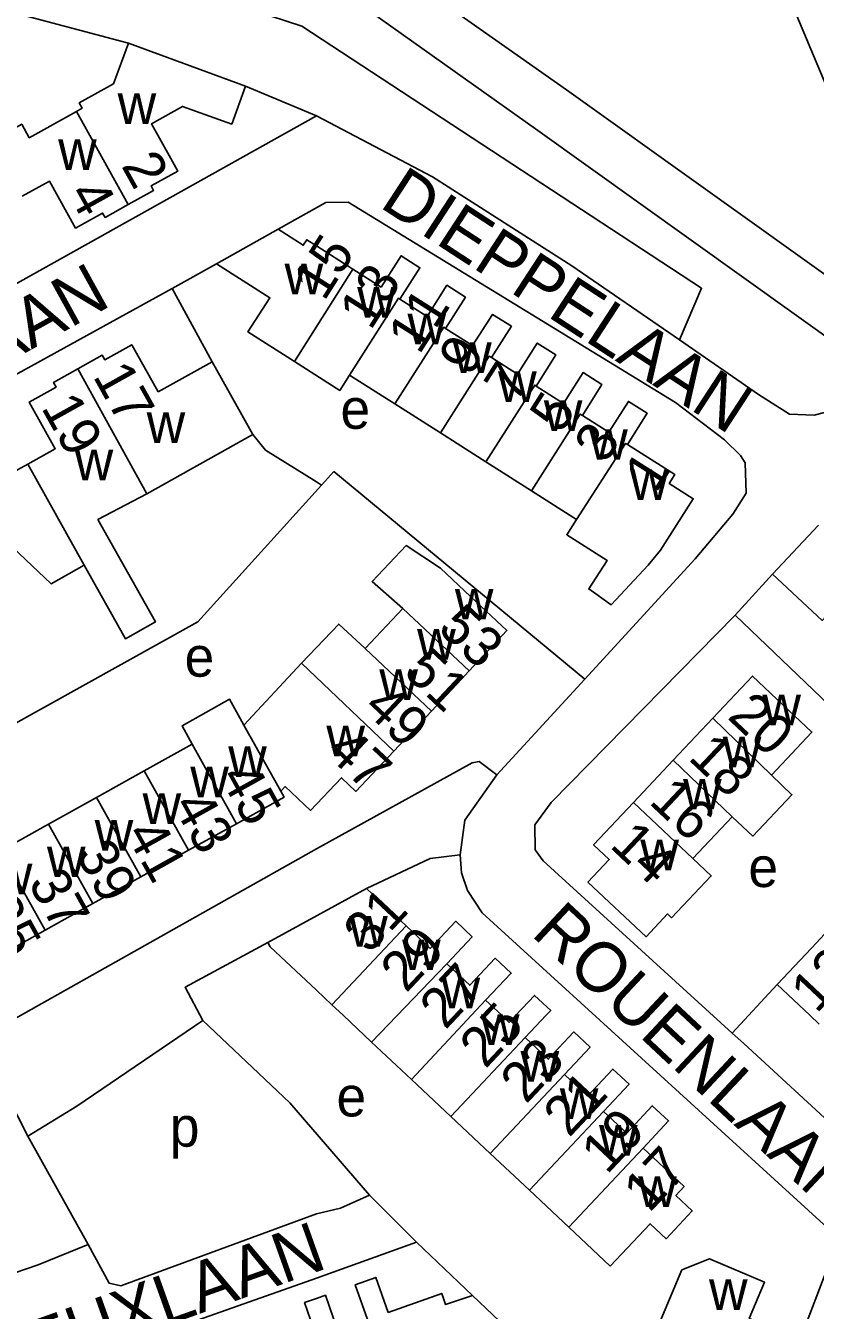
# Model space of a CAD drawing. Extents: x 157768 to 159790, y 387230 to 389604.
# Drawn here: x 159070.9 to 159150, y 389220.4 to 389349.2 of the extents above; entities that cross this region are included whole.
import ezdxf

# ---------------------------------------------------------------- set-up
doc = ezdxf.new("R2010")
doc.units = 0
for name, color, linetype in [('BLT_Basislijn', 7, 'Continuous'), ('BLT_Bebouwing', 7, 'Continuous'), ('BLT_Centroide', 7, 'Continuous'), ('BLT_Huisnummer', 7, 'Continuous'), ('BLT_Huisnummer_ tussenligend', 7, 'Continuous'), ('BLT_Onderverdeling_panden', 7, 'Continuous'), ('BLT_Straatnaam', 7, 'Continuous')]:
    doc.layers.add(name, color=color, linetype=linetype)

msp = doc.modelspace()

# ---------------------------------------------------------------- linework, layer by layer
at = {"layer": 'BLT_Basislijn'}
for p, q in [((159082, 389372.99), (159125.06, 389342.75)), ((159078.61, 389369.61), (159122.18, 389338.67)), ((159125.06, 389342.75), (159158.77, 389318.63)), ((159122.18, 389338.67), (159155.35, 389314.93)), ((159089.98, 389325.3), (159085.56, 389322.83)), ((159085.56, 389322.83), (159089.55, 389315.47)), ((159136.37, 389317.68), (159144.28, 389312.22)), ((159101.75, 389304.48), (159126.9, 389283.67)), ((159141.94, 389290.09), (159145.7, 389294.2)), ((159141.94, 389290.09), (159162.54, 389270.35)), ((159118.07, 389274.1), (159126.9, 389283.67)), ((159141.65, 389248.22), (159146.16, 389253.08)), ((159066.11, 389247.59), (159071.09, 389237.9)), ((159077.13, 389227.04), (159071.09, 389237.9)), ((159105.31, 389231.96), (159110.02, 389227.27))]:
    msp.add_line(p, q, dxfattribs=at)
for points in [[(159162.24, 389322.62), (159155.93, 389332.51), (159153.56, 389337.2), (159148.13, 389350.16), (159145.46, 389359.07), (159142.05, 389374.24), (159142.56, 389381.04), (159143.04, 389382.63), (159145.38, 389387.32), (159146.7, 389389.16), (159149.15, 389391.64), (159154.18, 389394.82), (159170.91, 389399.82), (159250.06, 389421.84), (159365.97, 389453.67), (159372.56, 389454.02), (159378.6, 389452.6), (159380.39, 389451.76), (159392.61, 389443.64), (159395.21, 389440.74), (159396.75, 389438.28), (159397.33, 389436.4), (159399.66, 389416.25), (159408.15, 389328.62)], [(159073.55, 389357.3), (159098.52, 389349.11), (159138.58, 389322.85), (159136.37, 389317.68)], [(159081.17, 389347.4), (159062.62, 389352.37), (159040.89, 389355.96), (159039.92, 389355.84), (158953.96, 389326.76), (158921.99, 389315.64)], [(159100, 389340.14), (159092.88, 389343.11)], [(159100, 389340.14), (159015.73, 389293.05), (159015.24, 389291.03), (159014.6, 389290.14), (159012.8, 389285.42), (158959.78, 389266), (158951.5, 389263.29), (158928.72, 389290.57)], [(159100, 389340.14), (159111.62, 389334.01), (159125.59, 389325.11), (159136.37, 389317.68)], [(159126.9, 389283.67), (159137.96, 389295.73), (159141.72, 389300.21), (159143.04, 389302.31), (159142.97, 389305.37), (159142.48, 389306.08), (159140.9, 389307.68), (159135.97, 389311.42), (159103.18, 389331.48), (159100.95, 389331.44), (159096.16, 389328.76)], [(159085.56, 389322.83), (159019.11, 389286.26), (159018.43, 389285.49), (159026.99, 389260.06), (159028.71, 389256.3)], [(159154.16, 389313.68), (159154.04, 389313.55), (159151.55, 389310.56), (159149.86, 389310.14), (159147.38, 389310.22), (159144.28, 389312.22)], [(159093.61, 389308.19), (159094.88, 389306.63), (159100, 389303.47), (159100.52, 389303.13)], [(159100.52, 389303.13), (159101.75, 389304.48)], [(159053.5, 389270.2), (159088.11, 389289.43), (159100.52, 389303.13)], [(159141.65, 389248.22), (159122.7, 389265.47), (159121.9, 389266.58), (159121.87, 389269.08), (159123.52, 389271.31), (159141.94, 389290.09)], [(159118.07, 389274.1), (159116.3, 389275.42), (159115.61, 389275.31), (159100, 389266.67), (159066.11, 389247.59)], [(159114.4, 389266.09), (159114.86, 389269.56), (159118.07, 389274.1)], [(159114.4, 389266.09), (159114.54, 389264.28), (159115.15, 389262.49), (159116.61, 389260.26), (159152.33, 389227.67), (159131.99, 389174.34), (159129.48, 389170.65), (159127.83, 389169.09), (159123.84, 389166.44), (159100, 389158.48), (159078.7, 389151.18)], [(159105.01, 389262.71), (159111.39, 389265.71), (159114.4, 389266.09)], [(159088.63, 389249.46), (159086.84, 389252.81), (159095.12, 389257.3)], [(159071.09, 389237.9), (159075.99, 389240.89), (159088.63, 389249.46)], [(159088.63, 389249.46), (159097.32, 389241.21), (159105.31, 389231.96)], [(159212, 389208.86), (159194.54, 389197.52), (159192.86, 389196.68), (159191.21, 389196.31), (159188.24, 389196.33), (159185.38, 389197.8), (159180.42, 389203.99), (159165.33, 389225.82), (159152.61, 389238.14), (159142.81, 389247.17), (159141.65, 389248.22)], [(159077.13, 389227.04), (159079.22, 389223.16), (159080.4, 389222.9), (159100, 389230.11), (159102.4, 389230.68), (159105.31, 389231.96)], [(159110.02, 389227.27), (159100, 389223.67), (159053.52, 389207.25)], [(159077.13, 389227.04), (159072.12, 389225), (159061.57, 389221.39)], [(159110.02, 389227.27), (159115.62, 389221.93)]]:
    msp.add_lwpolyline(points, dxfattribs=at)
at = {"layer": 'BLT_Bebouwing'}
for p, q in [((159084.14, 389312.46), (159089.55, 389315.47)), ((159089.55, 389315.47), (159093.61, 389308.19)), ((159107.86, 389311.26), (159103.31, 389314.15)), ((159112.42, 389308.36), (159107.86, 389311.26)), ((159093.61, 389308.19), (159083, 389302.26)), ((159116.97, 389305.47), (159112.42, 389308.36)), ((159121.53, 389302.57), (159116.97, 389305.47)), ((159126.06, 389299.69), (159121.53, 389302.57)), ((159150.31, 389299.12), (159145.7, 389294.2)), ((159108.65, 389290.77), (159104.87, 389286.74)), ((159115.3, 389284.53), (159111.52, 389280.49)), ((159111.52, 389280.49), (159107.74, 389276.46)), ((159135.74, 389275.55), (159139.72, 389279.77)), ((159087.54, 389277.16), (159082.75, 389274.49)), ((159131.76, 389271.33), (159135.74, 389275.55)), ((159082.75, 389274.49), (159077.96, 389271.82)), ((159077.96, 389271.82), (159073.17, 389269.15)), ((159073.17, 389269.15), (159068.38, 389266.48)), ((159091.98, 389269.2), (159087.19, 389266.53)), ((159137.72, 389265.71), (159141.66, 389269.89)), ((159087.19, 389266.53), (159082.4, 389263.86)), ((159082.4, 389263.86), (159077.61, 389261.19)), ((159105.01, 389262.71), (159108.99, 389258.97)), ((159077.61, 389261.19), (159072.82, 389258.52)), ((159072.82, 389258.52), (159068.03, 389255.85)), ((159109.51, 389243.58), (159105.53, 389247.31)), ((159113.48, 389239.84), (159109.51, 389243.58)), ((159117.41, 389236.15), (159113.48, 389239.84)), ((159121.35, 389232.46), (159117.41, 389236.15)), ((159125.28, 389228.76), (159121.35, 389232.46)), ((159115.62, 389221.93), (159119.7, 389218.06))]:
    msp.add_line(p, q, dxfattribs=at)
for points in [[(159075.95, 389340.58), (159076.54, 389340.91), (159076.24, 389341.43), (159079.68, 389343.35), (159081.17, 389347.4)], [(159081.17, 389347.4), (159092.88, 389343.11)], [(159092.88, 389343.11), (159091.52, 389339.3), (159086.59, 389341.07), (159083.49, 389339.34), (159085.59, 389335.55), (159086.12, 389334.6), (159083.44, 389333.11), (159083.69, 389332.66), (159081.14, 389331.24)], [(159067.44, 389337.58), (159070.48, 389339.28), (159071.23, 389337.94), (159075.95, 389340.58)], [(159070.51, 389332.08), (159073.24, 389333.59), (159075.86, 389328.88), (159078.57, 389330.39), (159078.82, 389329.95), (159081.14, 389331.24)], [(159089.98, 389325.3), (159096.16, 389328.76)], [(159096.16, 389328.76), (159098.68, 389327.16), (159099.03, 389327.71), (159100, 389327.09), (159103.66, 389324.76)], [(159103.66, 389324.76), (159106.48, 389322.97), (159108.48, 389326.11), (159110.37, 389324.91), (159108.36, 389321.76)], [(159097.79, 389315.52), (159093.14, 389318.47), (159095.33, 389321.9), (159089.98, 389325.3)], [(159108.36, 389321.76), (159111.09, 389320.03), (159113.08, 389323.15), (159114.93, 389321.97), (159112.93, 389318.83)], [(159112.93, 389318.83), (159115.65, 389317.11), (159117.64, 389320.24), (159119.53, 389319.04), (159117.53, 389315.9)], [(159076.1, 389314.78), (159078.54, 389316.14), (159078.79, 389315.69), (159081.49, 389317.2), (159084.14, 389312.46)], [(159117.53, 389315.9), (159120.14, 389314.24), (159122.12, 389317.36), (159123.99, 389316.17), (159122.02, 389313.05)], [(159103.31, 389314.15), (159102.34, 389312.62), (159097.79, 389315.52)], [(159071.09, 389305.24), (159073.83, 389306.77), (159071.22, 389311.44), (159073.92, 389312.95), (159073.66, 389313.42), (159076.1, 389314.78)], [(159122.02, 389313.05), (159124.76, 389311.31), (159126.72, 389314.4), (159128.61, 389313.2), (159126.64, 389310.11)], [(159126.64, 389310.11), (159129.29, 389308.42), (159131.26, 389311.52), (159133.14, 389310.33), (159131.15, 389307.21)], [(159060.37, 389306.04), (159062.8, 389307.39), (159063.07, 389306.9), (159065.75, 389308.39), (159068.36, 389303.72), (159071.09, 389305.24)], [(159131.15, 389307.21), (159135.92, 389304.18), (159135.35, 389303.29), (159137.75, 389301.76), (159134.48, 389296.61), (159133.23, 389295.1), (159129.52, 389291.14), (159127.29, 389292.73), (159129.14, 389295.56), (159125.82, 389297.68), (159125.08, 389298.15), (159126.06, 389299.69)], [(159083, 389302.26), (159078.11, 389299.68), (159083.87, 389289.41), (159080.86, 389287.73), (159076.74, 389295.09)], [(159076.74, 389295.09), (159073.43, 389293.25), (159068.24, 389298.12), (159065.61, 389296.65)], [(159115.3, 389284.53), (159119.08, 389288.56), (159115.44, 389291.98), (159112.43, 389294.8), (159109, 389297.06), (159105.58, 389293.47), (159108.65, 389290.77)], [(159145.7, 389294.2), (159150.66, 389289.56), (159152.78, 389291.83), (159154.81, 389294.01)], [(159104.87, 389286.74), (159102.23, 389289.2), (159098.51, 389285.27)], [(159098.51, 389285.27), (159092.74, 389279.08)], [(159139.72, 389279.77), (159143.7, 389283.99), (159147.33, 389280.55), (159149.65, 389278.37), (159145.58, 389274.05)], [(159092.74, 389279.08), (159092.32, 389279.82), (159091.28, 389281.69), (159086.53, 389278.99), (159087.54, 389277.16)], [(159096.43, 389272.45), (159096.87, 389272.91), (159099.42, 389270.52), (159102.5, 389273.8), (159103.96, 389272.43), (159107.74, 389276.46)], [(159141.66, 389269.89), (159143.73, 389267.95), (159147.64, 389272.1), (159145.58, 389274.05)], [(159091.98, 389269.2), (159096.76, 389271.86), (159096.43, 389272.45)], [(159137.72, 389265.71), (159139.56, 389263.97), (159135.56, 389259.78), (159135.17, 389260.15), (159133.02, 389257.86), (159127.2, 389263.35), (159129.34, 389265.61), (159127.77, 389267.09), (159131.76, 389271.33)], [(159095.12, 389257.3), (159105.01, 389262.71)], [(159108.99, 389258.97), (159111.4, 389256.7), (159113.96, 389259.42), (159115.6, 389257.87), (159113.06, 389255.17)], [(159146.16, 389253.08), (159149.59, 389256.73), (159151.81, 389259.09)], [(159101.55, 389251.05), (159100, 389252.51), (159095.36, 389256.86), (159095.12, 389257.3)], [(159113.06, 389255.17), (159115.36, 389253.01), (159117.91, 389255.72), (159119.52, 389254.21), (159116.95, 389251.51)], [(159150.38, 389249.11), (159149.43, 389250), (159146.16, 389253.08)], [(159105.53, 389247.31), (159102.67, 389250), (159101.55, 389251.05)], [(159116.95, 389251.51), (159118.56, 389250), (159119.31, 389249.29), (159119.98, 389250), (159121.85, 389251.99), (159123.47, 389250.47), (159123.03, 389250), (159120.91, 389247.76)], [(159120.91, 389247.76), (159123.22, 389245.59), (159125.8, 389248.33), (159127.42, 389246.81), (159124.85, 389244.08)], [(159124.85, 389244.08), (159127.16, 389241.91), (159129.7, 389244.61), (159131.33, 389243.09), (159128.77, 389240.37)], [(159128.77, 389240.37), (159131.09, 389238.2), (159133.65, 389240.93), (159135.28, 389239.41), (159132.73, 389236.69)], [(159132.73, 389236.69), (159136.84, 389232.84), (159136.01, 389231.95), (159137.66, 389230.4), (159135.03, 389227.6), (159133.42, 389229.11), (159129.43, 389224.86), (159125.28, 389228.76)], [(159142.18, 389214.18), (159144.3, 389219.22), (159143.36, 389219.62), (159144.9, 389223.25), (159139.37, 389225.59), (159136.62, 389224.48), (159134.67, 389219.87), (159133.77, 389217.74)], [(159107.18, 389220.23), (159105.95, 389223.73), (159103.88, 389222.99), (159105.1, 389219.51)], [(159102.12, 389218.46), (159100.9, 389221.94), (159100, 389221.62), (159098.81, 389221.21), (159100, 389217.74)], [(159115.62, 389221.93), (159112.94, 389221), (159112.55, 389222.12), (159107.18, 389220.23)]]:
    msp.add_lwpolyline(points, dxfattribs=at)
at = {"layer": 'BLT_Onderverdeling_panden'}
for p, q in [((159075.95, 389340.58), (159081.14, 389331.24)), ((159103.66, 389324.76), (159097.79, 389315.52)), ((159076.1, 389314.78), (159083, 389302.26)), ((159071.09, 389305.24), (159076.74, 389295.09)), ((159115.3, 389284.53), (159108.65, 389290.77)), ((159111.52, 389280.49), (159104.87, 389286.74)), ((159107.74, 389276.46), (159098.51, 389285.27)), ((159145.58, 389274.05), (159139.72, 389279.77)), ((159092.74, 389279.08), (159096.43, 389272.45)), ((159091.98, 389269.2), (159087.54, 389277.16)), ((159141.66, 389269.89), (159135.74, 389275.55)), ((159087.19, 389266.53), (159082.75, 389274.49)), ((159082.4, 389263.86), (159077.96, 389271.82)), ((159137.72, 389265.71), (159131.76, 389271.33)), ((159077.61, 389261.19), (159073.17, 389269.15)), ((159072.82, 389258.52), (159068.38, 389266.48)), ((159101.55, 389251.05), (159108.99, 389258.97)), ((159105.53, 389247.31), (159113.06, 389255.17)), ((159109.51, 389243.58), (159116.95, 389251.51)), ((159113.48, 389239.84), (159120.91, 389247.76)), ((159117.41, 389236.15), (159124.85, 389244.08)), ((159121.35, 389232.46), (159128.77, 389240.37)), ((159125.28, 389228.76), (159132.73, 389236.69))]:
    msp.add_line(p, q, dxfattribs=at)
for points in [[(159108.36, 389321.76), (159108.22, 389321.85), (159103.31, 389314.15)], [(159112.93, 389318.83), (159112.76, 389318.94), (159107.86, 389311.26)], [(159117.53, 389315.9), (159117.31, 389316.04), (159112.42, 389308.36)], [(159122.02, 389313.05), (159121.87, 389313.15), (159116.97, 389305.47)], [(159126.64, 389310.11), (159126.42, 389310.24), (159121.53, 389302.57)], [(159131.15, 389307.21), (159130.98, 389307.31), (159126.06, 389299.69)]]:
    msp.add_lwpolyline(points, dxfattribs=at)

# ---------------------------------------------------------------- texts
at = {"layer": 'BLT_Centroide'}
for s, p in [('w', (159080.08, 389339.31)), ('w', (159074.12, 389334.72)), ('w', (159096.81, 389322.23)), ('w', (159104.08, 389319.92)), ('w', (159109.12, 389317.25)), ('w', (159113.69, 389314.36)), ('w', (159118.2, 389311.44)), ('e', (159102.41, 389308.77)), ('w', (159122.78, 389308.56)), ('w', (159082.99, 389307.35)), ('w', (159127.33, 389305.66)), ('w', (159075.78, 389303.62)), ('w', (159131.42, 389301.64)), ('w', (159113.87, 389289.66)), ('w', (159110.09, 389285.62)), ('e', (159086.79, 389283.93)), ('w', (159106.3, 389281.59)), ('w', (159144.68, 389279.06)), ('w', (159101, 389275.94)), ('w', (159140.71, 389274.84)), ('w', (159091.16, 389273.89)), ('w', (159087.36, 389271.84)), ('w', (159136.73, 389270.62)), ('w', (159082.58, 389269.17)), ('w', (159077.78, 389266.5)), ('w', (159132.45, 389264.52)), ('w', (159073, 389263.84)), ('w', (159067.67, 389262.11)), ('e', (159143.28, 389262.85)), ('w', (159103.28, 389256.88)), ('w', (159108.58, 389254.52)), ('w', (159112.53, 389250.7)), ('w', (159116.48, 389247.03)), ('w', (159120.45, 389243.34)), ('e', (159102.01, 389239.86)), ('w', (159124.38, 389239.62)), ('p', (159085.31, 389236.83)), ('w', (159128.31, 389235.94)), ('w', (159132.23, 389230.78)), ('w', (159139.33, 389220.47))]:
    msp.add_text(s, height=4, dxfattribs=at).set_placement(p)
at = {"layer": 'BLT_Huisnummer'}
for s, rotation, p in [('2', 299.1288, (159080.4, 389335.14)), ('15', 57.5621, (159100.76, 389321.46)), ('9', 57.5621, (159115.39, 389313.92)), ('17', 299.1576, (159077.55, 389314.05)), ('5', 57.5621, (159124.51, 389308.18)), ('1', 57.5621, (159134, 389302.24)), ('53', 316.8342, (159112.02, 389288.61)), ('20', 316.6877, (159141.06, 389279.82)), ('47', 316.8398, (159100.79, 389276.25)), ('45', 299.1212, (159090.25, 389273.88)), ('14', 316.6884, (159129.28, 389266.91)), ('41', 299.1212, (159080.82, 389268.2)), ('37', 299.1212, (159071.05, 389263.27)), ('31', 46.8152, (159105.29, 389256.05)), ('12', 46.7342, (159150.09, 389250.09)), ('25', 46.8142, (159116.92, 389244.55)), ('21', 46.8144, (159125.31, 389237.67)), ('17', 46.7862, (159133.32, 389230.1))]:
    msp.add_text(s, height=4, rotation=rotation, dxfattribs=at).set_placement(p)
at = {"layer": 'BLT_Huisnummer_ tussenligend'}
for s, rotation, p in [('4', 299.1288, (159075.06, 389332.33)), ('13', 57.5621, (159105.42, 389318.54)), ('11', 57.5621, (159110.29, 389316.1)), ('7', 57.5621, (159119.96, 389311.23)), ('19', 299.1576, (159072.37, 389310.91)), ('3', 57.5621, (159128.97, 389305.16)), ('51', 316.8398, (159108.58, 389284.25)), ('49', 316.8398, (159104.56, 389280.64)), ('18', 316.6884, (159137.14, 389275.7)), ('16', 316.6884, (159133.2, 389271.31)), ('43', 299.1212, (159085.54, 389271.06)), ('39', 299.1212, (159075.81, 389266.16)), ('35', 299.1212, (159066.2, 389260.67)), ('29', 46.8142, (159108.99, 389252.16)), ('27', 46.8142, (159112.91, 389248.46)), ('23', 46.8144, (159121, 389241.03)), ('19', 46.7862, (159129.09, 389233.95))]:
    msp.add_text(s, height=4, rotation=rotation, dxfattribs=at).set_placement(p)
at = {"layer": 'BLT_Straatnaam'}
for s, rotation, p in [('DIEPPELAAN', 326.9017, (159106.2, 389331.06)), ('DIEPPELAAN', 28.9017, (159042.8, 389300.88)), ('ROUENLAAN', 316.9302, (159121.4, 389258.07)), ('EVREUXLAAN', 19.6643, (159058.89, 389209.57))]:
    msp.add_text(s, height=5, rotation=rotation, dxfattribs=at).set_placement(p)

doc.saveas('drawing.dxf')
